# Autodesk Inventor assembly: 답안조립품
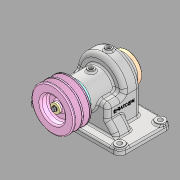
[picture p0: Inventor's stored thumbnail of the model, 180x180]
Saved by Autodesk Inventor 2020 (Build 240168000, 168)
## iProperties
Created: 2024-01
Part Number: 답안조립품
Document SubType Name: Assembly
Designer: 방송실
Author: 방송실
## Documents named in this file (16)
- C:\Users\방송실\Desktop\740104V1003\답안조립품.iam
- C:\Users\방송실\Desktop\740104V1003\본체.ipt
- C:\Users\방송실\Desktop\740104V1003\V-벨트 풀리.ipt
- C:\Users\방송실\Desktop\740104V1003\깊은 홈 볼 베어링 6202.ipt
- C:\Users\방송실\Desktop\740104V1003\뒷커버.ipt
- C:\Users\방송실\Desktop\740104V1003\스퍼 기어.ipt
- C:\Users\방송실\Desktop\740104V1003\앞커버.ipt
- C:\Users\방송실\Desktop\740104V1003\엔드 캡.ipt
- C:\Users\방송실\Desktop\740104V1003\오일 실 15 25 7.ipt
- C:\Users\방송실\Desktop\740104V1003\육각 머리 볼트 M4 x 12.ipt
- C:\Users\방송실\Desktop\740104V1003\육각 소켓 머리 볼트 M4 x 12.ipt
- C:\Users\방송실\Desktop\740104V1003\축.ipt
- C:\Users\방송실\Desktop\740104V1003\칼라.ipt
- C:\Users\방송실\Desktop\740104V1003\평와셔 M4.ipt
- C:\Users\방송실\Desktop\740104V1003\평행 키 3x3x12.ipt
- C:\Users\방송실\Desktop\740104V1003\평행 키 5x5x32.ipt
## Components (1 placed, 1 different names)
1. V-벨트 풀리:1
